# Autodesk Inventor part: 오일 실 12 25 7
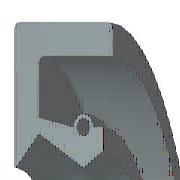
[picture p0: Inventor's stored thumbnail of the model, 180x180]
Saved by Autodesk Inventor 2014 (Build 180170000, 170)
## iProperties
IsCustomPart: 1
Created: 2012-02
Part Number: 오일 실 12 25 7
Material: 고무
Description: 오일-실
Document SubType Name: Modeling
Standard: KS B 2804
Designer: test
Standards Organization: KS
Language: ko-KR
Size Designation: D - 12 25 7
Categories: <MemberInstance><Categories><Category DisplayName="샤프트 부품" InternalName="7f7aeb1f-a693-4053-b835-cee3144e0d98" Mnemonic="SHFT"><Category DisplayName="실링" Intern
Density: 0.93 g/cm^3
Appearance: Rubber - Black - Version 1.1
Author: test
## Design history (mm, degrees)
revolve "본체" stored, may be unused: angle "d17" = 90 deg
revolve "스프링1" stored, may be unused: angle "d18" = 90 deg
body "Solid1"
sketch "스케치1"
  geometry: L1 (0, 12.5)-(7, 12.5); L2 (7, 10.75)-(1.75, 10.75); L3 (1.75, 7.75)-(4.9, 6); L4 (4.9, 6)-(0, 6); L5 (0, 0)-(9.586, 0) reference; L6 (4.9, 6)-(6.3, 6.875); L7 (0, 18)-(0, -3) reference; L8 (-1.941, 0)-(11.507, 0) reference; L9 (4.2, 8.1)-(1.75, 8.59); L10 (1.75, 8.59)-(1.75, 10.75); L11 (0, 12.5)-(0, 6.088); L12 (4.9, 6)-(0, 6); L13 (1.75, 7.75)-(0.152, 6.028); L14 (7, 12.5)-(7, 10.75); L15 (5.6, 8.1)-(6.3, 8.1); L16 (6.3, 8.1)-(6.3, 6.875); C1 r 0.455 at (4.9, 8.1); A1 r 0.7 centre (4.9, 8.1) between (5.6, 8.1) and (4.2, 8.1); A2 r 0.088 centre (0.088, 6.088) between (0, 6.088) and (0.152, 6.028); 1 further point
  constraints: 28 end point, 5 horizontal alignment, 5 point on line, 4 point on circle, 4 vertical alignment, 3 centre point, 3 tangent, 2 collinear, 2 horizontal, 2 perpendicular, 1 coincident, 1 parallel
  dimensions: "d0" = 25 diameter of L1 L5 (= SD2); "d1" = 1.75 distance of L1.end L2.start (= SD); "d2" = 0.91 diameter of C1 (= SPDI); "d3" = 1.4 diameter of A1 (= SPDA); "d4" = 12 diameter of L3.end L5 (= NND); "d5" = 15.5 diameter of L3.start L5 (= TKDM); "d7" = 17.18 diameter of L9.end L5 (= TKDM + 0.24 x SWDT); "d8" = 1.75 distance between parallel lines of L11 L10 (= SD); "d9" = 4.9 distance from line of L11 C1.centre (= SPDST); "d10" = 16.2 diameter of C1.centre L5 (= HLDM); "d11" = 0.0875 radius of A2 (= 0.25 x LAB); "d12" = 6.3 distance between parallel lines of L11 L16 (= SDI); "d13" = 13.75 diameter of L6.end L5 (= ABDM); "d14" = 7 distance from line of L11 L1.end (= SWDT)
fillet "모깎기1" dims "d6" = 0.3 (= RR)
other parameters: "SD2" = 25 [user parameter; used in 1 equation term], "SWDT" = 7 [user parameter; used in 2 equation terms], "RR" = 0.3 [user parameter; used in 1 equation term], "SD" = 1.75 [user parameter; used in 2 equation terms], "NND" = 12 [user parameter; used in 1 equation term], "SPDA" = 1.4 [user parameter; used in 1 equation term], "SPDI" = 0.91 [user parameter; used in 1 equation term], "TKDM" = 15.5 [user parameter; used in 2 equation terms], "HLDM" = 16.2 [user parameter; used in 1 equation term], "ABDM" = 13.75 [user parameter; used in 1 equation term], "SDI" = 6.3 [user parameter; used in 1 equation term], "SPDST" = 4.9 [user parameter; used in 1 equation term], "LAB" = 0.35 [user parameter; used in 1 equation term], "d15" = 0, "d16" = 0, "d19" = 0
